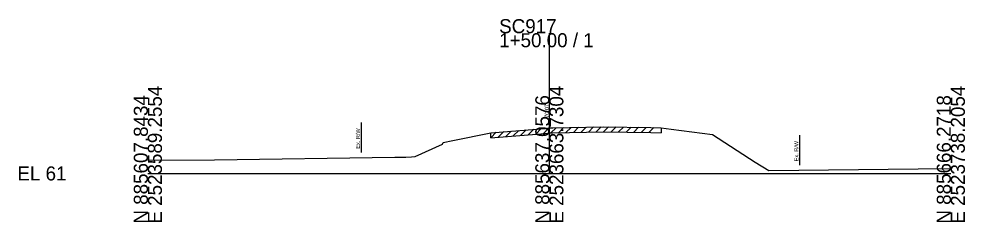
# Model space of a CAD drawing. Extents: x -26 to 218, y -10 to 12021.
# Drawn here: x -25.7 to 162.8, y 1490.3 to 1530.8 of the extents above; entities that cross this region are included whole.
import ezdxf

# ---------------------------------------------------------------- set-up
doc = ezdxf.new("R2010")
doc.units = 0
for name, color, linetype in [('RD_GPK_XS_Cell', 7, 'Continuous'), ('RD_XS_ExGround', 7, 'Continuous'), ('RD_XS_ExPaveRet', 7, 'Continuous'), ('RD_XS_ExRW', 7, 'Continuous'), ('RD_XS_TX_Elev_EX', 7, 'Continuous')]:
    doc.layers.add(name, color=color, linetype=linetype)

msp = doc.modelspace()

# ---------------------------------------------------------------- linework, layer by layer
at = {"layer": 'RD_GPK_XS_Cell'}
for p, q in [((80, 1500), (80, 1527.95)), ((0, 1500), (80, 1500)), ((80, 1500), (160, 1500))]:
    msp.add_line(p, q, dxfattribs=at)
at = {"layer": 'RD_XS_ExGround'}
for p, q in [((68.31, 1508.11), (79.08, 1508.99)), ((79.08, 1508.99), (80.09, 1509.07)), ((80.09, 1509.07), (80.67, 1509.09)), ((80.67, 1509.09), (90.71, 1509.32)), ((90.71, 1509.32), (100.22, 1509.15)), ((100.22, 1509.15), (102.27, 1509.12)), ((102.27, 1509.12), (104.29, 1508.85)), ((104.29, 1508.85), (112.48, 1507.74)), ((58.87, 1506.18), (60.79, 1506.59)), ((60.79, 1506.59), (68.31, 1508.11)), ((112.48, 1507.74), (121.04, 1502.23)), ((53.24, 1503.4), (58.7, 1505.81)), ((58.7, 1505.81), (58.87, 1506.18)), ((0, 1502.64), (13.27, 1502.74)), ((13.27, 1502.74), (49.18, 1503.25)), ((49.18, 1503.25), (51.38, 1503.26)), ((51.38, 1503.26), (52.54, 1503.31)), ((52.54, 1503.31), (53.24, 1503.4)), ((121.04, 1502.23), (123.75, 1500.57)), ((123.75, 1500.57), (153.49, 1500.9)), ((153.49, 1500.9), (160, 1500.97))]:
    msp.add_line(p, q, dxfattribs=at)
at = {"layer": 'RD_XS_ExPaveRet'}
for p, q in [((69.81, 1507.24), (70.9, 1508.33)), ((71.31, 1507.36), (72.4, 1508.45)), ((72.81, 1507.48), (73.9, 1508.57)), ((74.31, 1507.6), (75.4, 1508.69)), ((75.81, 1507.72), (76.9, 1508.81)), ((77.31, 1507.85), (78.4, 1508.93)), ((78.81, 1507.97), (79.9, 1509.06)), ((80.31, 1508.08), (81.33, 1509.1)), ((80.67, 1508.09), (90.71, 1508.32)), ((81.81, 1508.11), (82.83, 1509.14)), ((83.31, 1508.15), (84.33, 1509.17)), ((84.81, 1508.18), (85.83, 1509.21)), ((86.31, 1508.22), (87.33, 1509.24)), ((87.81, 1508.25), (88.83, 1509.27)), ((89.31, 1508.29), (90.33, 1509.31)), ((90.71, 1508.32), (100.22, 1508.15)), ((90.81, 1508.32), (91.79, 1509.3)), ((92.31, 1508.29), (93.29, 1509.27)), ((93.81, 1508.26), (94.79, 1509.25)), ((95.31, 1508.24), (96.29, 1509.22)), ((96.81, 1508.21), (97.79, 1509.2)), ((98.31, 1508.19), (99.29, 1509.17)), ((99.81, 1508.16), (100.79, 1509.14)), ((102.27, 1509.12), (102.27, 1508.12)), ((68.31, 1507.11), (69.4, 1508.2)), ((68.31, 1507.11), (68.31, 1508.11)), ((68.31, 1507.11), (79.08, 1507.99)), ((79.08, 1507.99), (80.09, 1508.07)), ((80.09, 1508.07), (80.67, 1508.09)), ((100.22, 1508.15), (102.27, 1508.12))]:
    msp.add_line(p, q, dxfattribs=at)
at = {"layer": 'RD_XS_ExRW'}
for p, q in [((42.5, 1510.16), (42.5, 1504.16)), ((129.87, 1507.64), (129.87, 1501.64))]:
    msp.add_line(p, q, dxfattribs=at)

# ---------------------------------------------------------------- texts
at = {"layer": 'RD_GPK_XS_Cell'}
for s, p in [('SC917', (70, 1527.95)), ('1+50.00 / 1', (70, 1525.15)), ('EL 61', (-26, 1498.6))]:
    msp.add_text(s, height=2.8, dxfattribs=at).set_placement(p)
for s, p in [('E 2523589.2554', (2.8, 1490)), ('E 2523663.7304', (82.8, 1490)), ('E 2523738.2054', (162.8, 1490)), ('N 885607.8434', (0, 1490)), ('N 885637.0576', (80, 1490)), ('N 885666.2718', (160, 1490))]:
    msp.add_text(s, height=2.8, rotation=90, dxfattribs=at).set_placement(p)
at = {"layer": 'RD_XS_ExRW'}
for p in [(42.25, 1504.94), (129.62, 1502.42)]:
    msp.add_text('Ex. R/W ', height=0.8, rotation=90, dxfattribs=at).set_placement(p)
at = {"layer": 'RD_XS_TX_Elev_EX'}
msp.add_text('70.07', height=0.8, rotation=90, dxfattribs=at).set_placement((79.9, 1511.07))

doc.saveas('drawing.dxf')
